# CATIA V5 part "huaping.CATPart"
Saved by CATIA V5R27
Part number: flower
Material "Water": density 1000 kg/m3
Material "Multicoloured Flag"
Material "Chessboard": density 2500 kg/m3
Bounding box of the stored display mesh (mm): x -45.563 to 45.563, y -45.563 to 61.991, z 0 to 139.66
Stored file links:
  G:\3D工程制图\180132104于洋\flower.CATPart
  E:\Program Files\Dassault Systemes\B27\win_b64\startup\materials\Catalog.CATMaterial
  E:\Program Files\Dassault Systemes\B27\win_b64\startup\materials\teak_2.jpg
  E:\Program Files\Dassault Systemes\B27\win_b64\startup\materials\cedar.jpg
  E:\Program Files\Dassault Systemes\B27\win_b64\startup\materials\blue_env_512x512.jpg
  E:\Program Files\Dassault Systemes\B27\win_b64\startup\materials\DS_star.jpg
  E:\Program Files\Dassault Systemes\B27\win_b64\startup\materials\chessboard.jpg
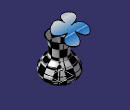
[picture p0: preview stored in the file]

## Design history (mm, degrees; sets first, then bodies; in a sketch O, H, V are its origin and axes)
Body1 (main body), material "Chessboard"
  Plane1: type Offset, RefPlane xy-plane, Offset 20
  Plane2: type Offset, RefPlane Plane1, Offset 20
  Plane3: type Offset, RefPlane Plane2, Offset 20
  Plane4: type Offset, RefPlane Plane3, Offset 20
  Plane5: type Offset, RefPlane Plane4, Offset 20
  Sketch1 on Plane5, origin (0, 0, 100), H (1, 0, 0), V (0, 1, 0)
    circle A1 centre (0, 0) radius 29.8266
  Sketch2 on Plane4, origin (0, 0, 80), H (1, 0, 0), V (0, 1, 0)
    circle A1 centre (0, 0) radius 23.0726
  Sketch3 on Plane3, origin (0, 0, 60), H (1, 0, 0), V (0, 1, 0)
    circle A1 centre (0, 0) radius 21.9749
  Sketch4 on Plane2, origin (0, 0, 40), H (1, 0, 0), V (0, 1, 0)
    circle A1 centre (0, 0) radius 37.8812
  Sketch5 on Plane1, origin (0, 0, 20), H (1, 0, 0), V (0, 1, 0)
    circle A1 centre (0, 0) radius 45.607
  Sketch6 on xy-plane, origin (0, 0, 0), H (1, 0, 0), V (0, 1, 0)
    circle A1 centre (0, 0) radius 31.6229
  Loft1: solid, Sections (Sketch1; Sketch2; Sketch3; Sketch4; Sketch5; Sketch6)
  Shell1: ExtOffset 0, Face face of Loft1, IntOffset 1
Body2, material "Water"
  Sketch7 on yz-plane, origin (0, 0, 0), H (0, 1, 0), V (0, 0, 1)
    axis line L1 (0, 117.0904) -> (0, -14.88)
    point P1 (0, 117.0904)
    line L2 (0, 0) -> (30.5626, 0)
    line L3 (30.5626, 0) -> (41.5502, 9.897)
    line L4 (41.5502, 9.897) -> (44.4279, 15.6349)
    line L5 (44.4279, 15.6349) -> (44.4279, 21.6335)
    line L6 (44.4279, 21.6335) -> (43.1199, 28.9362)
    line L7 (43.1199, 28.9362) -> (0, 28.9362)
    point P8 (0, 28.9362)
    line L8 (0, 28.9362) -> (0, 0)
    coincidence: P1 V, P8 L1
    vertical: L1 V, L5 V, L8 V
    horizontal: L2 H, L7 H
  Shaft1: profile Sketch7, axis Sketch7.L1, angle 360
Body3, material "Multicoloured Flag"
  Sketch8 on yz-plane, origin (0, 0, 0), H (0, 1, 0), V (0, 0, 1)
    spline S1 through (4.925, 3.3767) (15.651, 101.1809) (24.5457, 125.9579)
    point P1 (24.5457, 125.9579)
    point P2 (24.5457, 125.9579)
    coincidence: P1 P2
  Plane6: type Normal, Curve Sketch8, RefPoint vertex of Sketch8
  Sketch9 on Plane6, origin (0, -0.2087, 3.0221), H (-1, 0, 0), V (0, 0.9976, 0.0689)
    circle A1 centre (0, 4.9123) radius 1
    point P1 (0, 4.9123)
    radius A1 = 1
    coincidence: P1 V
  Rib1: profile Sketch9, centre curve Sketch8
  Plane7: type OffsetPt, RefPlane zx-plane, RefPoint Sketch8.P2
  Plane8: type Normal, Curve Sketch8, RefPoint Sketch8.P2
  Sketch10 on Plane8, origin (0, 48.2205, 116.1272), H (1, 0, 0), V (0, -0.9235, 0.3835)
    spline S1 through (-4.3423, 41.7545) (-19.2273, 61.1433) (-37.8855, 41.7545) (-12.0228, 30.6751) (-40.4521, 21.5134) (-23.8706, -3.9187) (-8.5786, 13.9217) (2.1878, -12.1777) (28.996, 6.7624) (7.7842, 19.0587) (34.5873, 27.8468) (18.1132, 54.0973) (-4.3423, 41.7545)
    point P1 (-4.3423, 41.7545)
    point P2 (-4.3423, 41.7545)
    coincidence: P1 P2
  Pad1: profile Sketch10, direction (0, -0.3835, -0.9235), length 1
